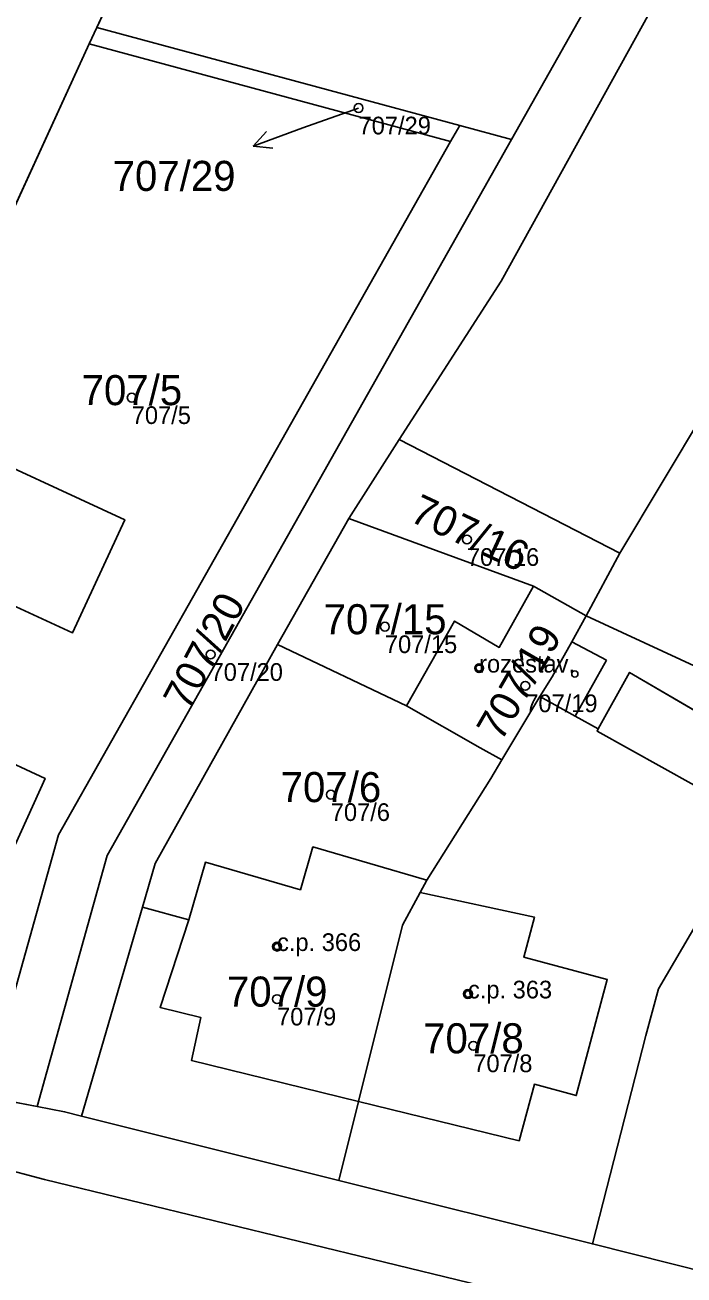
# Model space of a CAD drawing. Extents: x -603967 to -594699, y -1179315 to -1165625.
# Drawn here: x -598433.1 to -598395.8, y -1172192.7 to -1172122 of the extents above; entities that cross this region are included whole.
import ezdxf

# ---------------------------------------------------------------- set-up
doc = ezdxf.new("R2010")
doc.units = 0
for name, color, linetype in [('Definiční body', 7, 'Continuous'), ('Hranice parcel', 7, 'Continuous'), ('Parcelní čísla', 7, 'Continuous'), ('Polygon budovy', 7, 'Continuous'), ('Polygon parcely', 7, 'Continuous'), ('Pop  PČ popisy', 7, 'Continuous'), ('Vnitřní kresba', 7, 'Continuous'), ('Značky budov', 7, 'Continuous')]:
    doc.layers.add(name, color=color, linetype=linetype)

msp = doc.modelspace()

# ---------------------------------------------------------------- linework, layer by layer
at = {"layer": 'Definiční body'}
for centre in [(-598414.22, -1172126.68994), (-598427.05, -1172143.05994), (-598408.09, -1172151.07994), (-598412.73, -1172156.00994), (-598422.59, -1172157.57994), (-598407.4, -1172158.34994), (-598404.79, -1172159.34994), (-598415.79, -1172165.49994), (-598418.83, -1172174.08994), (-598418.83, -1172177.05994), (-598408.03, -1172176.76994), (-598407.73, -1172179.69994)]:
    msp.add_circle(centre, 0.25, dxfattribs=at)
at = {"layer": 'Hranice parcel'}
for p, q in [((-598427.41, -1172118.62), (-598429.02, -1172122.13)), ((-598429.45, -1172123.06), (-598429.02, -1172122.13)), ((-598429.02, -1172122.13), (-598408.49, -1172127.67)), ((-598429.45, -1172123.06), (-598454.41, -1172177.46)), ((-598409.01, -1172128.58), (-598429.45, -1172123.06)), ((-598408.49, -1172127.67), (-598409.01, -1172128.58)), ((-598408.49, -1172127.67), (-598405.56, -1172128.46)), ((-598405.56, -1172128.46), (-598428.45, -1172168.95)), ((-598411.92, -1172145.43), (-598414.77, -1172149.9)), ((-598411.92, -1172145.43), (-598399.44, -1172151.86)), ((-598414.77, -1172149.9), (-598418.8, -1172157.01)), ((-598404.32, -1172153.72), (-598414.77, -1172149.9)), ((-598399.44, -1172151.86), (-598401.34, -1172155.39)), ((-598404.32, -1172153.72), (-598401.34, -1172155.39)), ((-598411.51, -1172160.49), (-598418.8, -1172157.01)), ((-598403.96, -1172159.95), (-598406.11, -1172163.53)), ((-598401.96, -1172161.06), (-598403.96, -1172159.95)), ((-598428.45, -1172168.95), (-598432.4, -1172183.13)), ((-598426.45, -1172171.87), (-598429.9, -1172183.67)), ((-598435.36, -1172182.56), (-598432.4, -1172183.13)), ((-598429.9, -1172183.67), (-598415.34, -1172187.31)), ((-598415.34, -1172187.31), (-598400.99, -1172190.9)), ((-598400.99, -1172190.9), (-598394.33, -1172192.57))]:
    msp.add_line(p, q, dxfattribs=at)
for points in [[(-598343.23, -1172054.29), (-598392.25, -1172139.87), (-598399.44, -1172151.86)], [(-598366.76, -1172065.25), (-598406.16, -1172136.47), (-598411.92, -1172145.43)], [(-598405.56, -1172128.46), (-598370.96, -1172067.25), (-598366.76, -1172065.25)], [(-598434.82, -1172180.65), (-598431.19, -1172167.78), (-598409.01, -1172128.58)], [(-598437.97, -1172161.8), (-598431.95, -1172164.58), (-598434.74, -1172170.72), (-598443.6, -1172166.69), (-598442.75, -1172164.8), (-598445.63, -1172163.48), (-598437.33, -1172145.4), (-598427.45, -1172149.96), (-598430.41, -1172156.36), (-598434.59, -1172154.44), (-598437.97, -1172161.8)], [(-598411.51, -1172160.49), (-598408.79, -1172155.69), (-598406.26, -1172157.18), (-598404.32, -1172153.72)], [(-598401.34, -1172155.39), (-598402.16, -1172156.87), (-598403.26, -1172158.84), (-598403.96, -1172159.95)], [(-598401.34, -1172155.39), (-598391.69, -1172159.86), (-598388.43, -1172161.42)], [(-598418.8, -1172157.01), (-598425.72, -1172169.39), (-598426.45, -1172171.87)], [(-598406.11, -1172163.53), (-598407.35, -1172162.86), (-598411.51, -1172160.49)], [(-598395.24, -1172164.96), (-598400.73, -1172161.91), (-598400.66, -1172161.78), (-598401.96, -1172161.06)], [(-598410.35, -1172170.34), (-598406.74, -1172164.59), (-598406.11, -1172163.53)], [(-598391.7, -1172166.99), (-598397.26, -1172176.48), (-598397.97, -1172179.11), (-598400.99, -1172190.9)], [(-598426.45, -1172171.87), (-598423.83, -1172172.58), (-598422.88, -1172169.32), (-598417.51, -1172170.88), (-598416.8, -1172168.46), (-598410.35, -1172170.34)], [(-598410.35, -1172170.34), (-598410.73, -1172171.04), (-598411.73, -1172172.88), (-598414.22, -1172182.85), (-598415.34, -1172187.31)], [(-598432.4, -1172183.13), (-598430.85, -1172183.43), (-598429.9, -1172183.67)]]:
    msp.add_lwpolyline(points, dxfattribs=at)
at = {"layer": 'Polygon budovy'}
for points in [[(-598437.97, -1172161.8), (-598434.59, -1172154.44), (-598430.41, -1172156.36), (-598427.45, -1172149.96), (-598437.33, -1172145.4), (-598445.63, -1172163.48), (-598442.75, -1172164.8), (-598443.6, -1172166.69), (-598434.74, -1172170.72), (-598431.95, -1172164.58)], [(-598411.51, -1172160.49), (-598407.35, -1172162.86), (-598406.11, -1172163.53), (-598403.96, -1172159.95), (-598403.26, -1172158.84), (-598402.16, -1172156.87), (-598401.34, -1172155.39), (-598404.32, -1172153.72), (-598406.26, -1172157.18), (-598408.79, -1172155.69)], [(-598400.66, -1172161.78), (-598400.73, -1172161.91), (-598395.24, -1172164.96), (-598394.91, -1172165.17), (-598391.7, -1172166.99), (-598388.43, -1172161.42), (-598391.69, -1172159.86), (-598392.9, -1172162.1), (-598398.89, -1172158.59)], [(-598423.83, -1172172.58), (-598425.45, -1172177.53), (-598423.14, -1172178.1), (-598423.67, -1172180.53), (-598414.22, -1172182.85), (-598411.73, -1172172.88), (-598410.73, -1172171.04), (-598410.35, -1172170.34), (-598416.8, -1172168.46), (-598417.51, -1172170.88), (-598422.88, -1172169.32)], [(-598411.73, -1172172.88), (-598414.22, -1172182.85), (-598405.14, -1172185.07), (-598404.27, -1172181.87), (-598401.91, -1172182.51), (-598400.79, -1172178.35), (-598400.15, -1172175.96), (-598404.88, -1172174.69), (-598404.27, -1172172.42), (-598410.73, -1172171.04)]]:
    msp.add_lwpolyline(points, close=True, dxfattribs=at)
at = {"layer": 'Polygon parcely'}
for points in [[(-598346, -1172088.22), (-598308.31, -1172023.09), (-598317.51, -1172020.84), (-598343.23, -1172054.29), (-598392.25, -1172139.87), (-598399.44, -1172151.86), (-598401.34, -1172155.39), (-598391.69, -1172159.86), (-598388.43, -1172161.42), (-598385.73, -1172156.81), (-598378.06, -1172143.31)], [(-598399.44, -1172151.86), (-598392.25, -1172139.87), (-598343.23, -1172054.29), (-598366.76, -1172065.25), (-598406.16, -1172136.47), (-598411.92, -1172145.43)], [(-598427.41, -1172118.62), (-598429.02, -1172122.13), (-598408.49, -1172127.67), (-598405.56, -1172128.46), (-598370.96, -1172067.25), (-598366.76, -1172065.25), (-598364.01, -1172060.34), (-598367.75, -1172062.11), (-598403.85, -1172079.17), (-598410.83, -1172082.12), (-598411.43, -1172082.37), (-598412.86, -1172087)], [(-598428.45, -1172168.95), (-598432.4, -1172183.13), (-598430.85, -1172183.43), (-598429.9, -1172183.67), (-598426.45, -1172171.87), (-598425.72, -1172169.39), (-598418.8, -1172157.01), (-598414.77, -1172149.9), (-598411.92, -1172145.43), (-598406.16, -1172136.47), (-598366.76, -1172065.25), (-598370.96, -1172067.25), (-598405.56, -1172128.46)], [(-598460.01, -1172174.07), (-598460.86, -1172175.93), (-598454.41, -1172177.46), (-598429.45, -1172123.06), (-598429.02, -1172122.13), (-598427.41, -1172118.62), (-598433.32, -1172115.91), (-598434.26, -1172117.63), (-598435.72, -1172120.79), (-598437.07, -1172124.09), (-598441.66, -1172133.89), (-598444.29, -1172139.66), (-598450, -1172152.26)], [(-598429.45, -1172123.06), (-598409.01, -1172128.58), (-598408.49, -1172127.67), (-598429.02, -1172122.13)], [(-598429.45, -1172123.06), (-598454.41, -1172177.46), (-598444.32, -1172180.02), (-598441.78, -1172180.84), (-598441.27, -1172178.91), (-598434.82, -1172180.65), (-598431.19, -1172167.78), (-598409.01, -1172128.58)], [(-598435.36, -1172182.56), (-598432.4, -1172183.13), (-598428.45, -1172168.95), (-598405.56, -1172128.46), (-598408.49, -1172127.67), (-598409.01, -1172128.58), (-598431.19, -1172167.78), (-598434.82, -1172180.65)], [(-598437.97, -1172161.8), (-598431.95, -1172164.58), (-598434.74, -1172170.72), (-598443.6, -1172166.69), (-598442.75, -1172164.8), (-598445.63, -1172163.48), (-598437.33, -1172145.4), (-598427.45, -1172149.96), (-598430.41, -1172156.36), (-598434.59, -1172154.44)], [(-598437.97, -1172161.8), (-598434.59, -1172154.44), (-598430.41, -1172156.36), (-598427.45, -1172149.96), (-598437.33, -1172145.4), (-598445.63, -1172163.48), (-598442.75, -1172164.8), (-598443.6, -1172166.69), (-598434.74, -1172170.72), (-598431.95, -1172164.58)], [(-598404.32, -1172153.72), (-598401.34, -1172155.39), (-598399.44, -1172151.86), (-598411.92, -1172145.43), (-598414.77, -1172149.9)], [(-598414.77, -1172149.9), (-598418.8, -1172157.01), (-598411.51, -1172160.49), (-598408.79, -1172155.69), (-598406.26, -1172157.18), (-598404.32, -1172153.72)], [(-598411.51, -1172160.49), (-598407.35, -1172162.86), (-598406.11, -1172163.53), (-598403.96, -1172159.95), (-598403.26, -1172158.84), (-598402.16, -1172156.87), (-598401.34, -1172155.39), (-598404.32, -1172153.72), (-598406.26, -1172157.18), (-598408.79, -1172155.69)], [(-598403.96, -1172159.95), (-598401.96, -1172161.06), (-598400.66, -1172161.78), (-598400.73, -1172161.91), (-598395.24, -1172164.96), (-598394.91, -1172165.17), (-598391.7, -1172166.99), (-598388.43, -1172161.42), (-598391.69, -1172159.86), (-598401.34, -1172155.39), (-598402.16, -1172156.87), (-598403.26, -1172158.84)], [(-598426.45, -1172171.87), (-598423.83, -1172172.58), (-598422.88, -1172169.32), (-598417.51, -1172170.88), (-598416.8, -1172168.46), (-598410.35, -1172170.34), (-598406.74, -1172164.59), (-598406.11, -1172163.53), (-598407.35, -1172162.86), (-598411.51, -1172160.49), (-598418.8, -1172157.01), (-598425.72, -1172169.39)], [(-598391.7, -1172166.99), (-598397.26, -1172176.48), (-598397.97, -1172179.11), (-598400.99, -1172190.9), (-598394.33, -1172192.57), (-598386.4, -1172194.56), (-598386.11, -1172193.41), (-598385.26, -1172189.95), (-598384.3, -1172186.01), (-598383.07, -1172181.2), (-598382.7, -1172180.09), (-598373.36, -1172163.76), (-598376.38, -1172162.04), (-598382.7, -1172158.44), (-598385.73, -1172156.81), (-598388.43, -1172161.42)], [(-598415.34, -1172187.31), (-598400.99, -1172190.9), (-598397.97, -1172179.11), (-598397.26, -1172176.48), (-598391.7, -1172166.99), (-598394.91, -1172165.17), (-598395.24, -1172164.96), (-598400.73, -1172161.91), (-598400.66, -1172161.78), (-598401.96, -1172161.06), (-598403.96, -1172159.95), (-598406.11, -1172163.53), (-598406.74, -1172164.59), (-598410.35, -1172170.34), (-598410.73, -1172171.04), (-598411.73, -1172172.88), (-598414.22, -1172182.85)], [(-598429.9, -1172183.67), (-598415.34, -1172187.31), (-598414.22, -1172182.85), (-598411.73, -1172172.88), (-598410.73, -1172171.04), (-598410.35, -1172170.34), (-598416.8, -1172168.46), (-598417.51, -1172170.88), (-598422.88, -1172169.32), (-598423.83, -1172172.58), (-598426.45, -1172171.87)]]:
    msp.add_lwpolyline(points, close=True, dxfattribs=at)
msp.add_lwpolyline([(-598394.33, -1172192.57), (-598400.99, -1172190.9), (-598415.34, -1172187.31), (-598429.9, -1172183.67), (-598430.85, -1172183.43), (-598432.4, -1172183.13), (-598435.36, -1172182.56), (-598441.78, -1172180.84), (-598444.32, -1172180.02), (-598454.41, -1172177.46), (-598460.86, -1172175.93), (-598479.25, -1172171.56), (-598499.17, -1172166.38), (-598502.57, -1172165.76), (-598506.46, -1172165.08), (-598504.99, -1172168.27), (-598501.82, -1172175.18), (-598501.14, -1172176.66), (-598500.47, -1172178.12), (-598499.17, -1172178.46), (-598442.4, -1172193.44), (-598434.3, -1172195.58), (-598398.67, -1172204.06), (-598380.14, -1172209.25)], dxfattribs=at)
at = {"layer": 'Pop  PČ popisy'}
for p, q in [((-598414.22, -1172126.69), (-598417.37, -1172127.81)), ((-598417.37, -1172127.81), (-598420.19, -1172128.836)), ((-598420.19, -1172128.836), (-598419.42, -1172128.023)), ((-598420.19, -1172128.836), (-598419.078, -1172128.964))]:
    msp.add_line(p, q, dxfattribs=at)
at = {"layer": 'Vnitřní kresba'}
for p, q in [((-598402.16, -1172156.87), (-598400.19, -1172157.9)), ((-598400.19, -1172157.9), (-598401.96, -1172161.06)), ((-598400.66, -1172161.78), (-598398.89, -1172158.59)), ((-598398.89, -1172158.59), (-598392.9, -1172162.1)), ((-598431.98, -1172187.25), (-598497.9, -1172169.95)), ((-598404.27, -1172172.42), (-598410.73, -1172171.04)), ((-598425.45, -1172177.53), (-598423.83, -1172172.58)), ((-598404.88, -1172174.69), (-598404.27, -1172172.42)), ((-598400.15, -1172175.96), (-598404.88, -1172174.69)), ((-598400.79, -1172178.35), (-598400.15, -1172175.96)), ((-598423.14, -1172178.1), (-598425.45, -1172177.53)), ((-598423.67, -1172180.53), (-598423.14, -1172178.1)), ((-598401.91, -1172182.51), (-598400.79, -1172178.35)), ((-598414.22, -1172182.85), (-598423.67, -1172180.53)), ((-598405.14, -1172185.07), (-598404.27, -1172181.87)), ((-598404.27, -1172181.87), (-598401.91, -1172182.51)), ((-598405.14, -1172185.07), (-598414.22, -1172182.85)), ((-598395.71, -1172196.06), (-598431.98, -1172187.25))]:
    msp.add_line(p, q, dxfattribs=at)
at = {"layer": 'Značky budov'}
for centre in [(-598407.4068, -1172158.34916), (-598401.9868, -1172158.67916), (-598418.8368, -1172174.08916), (-598408.0368, -1172176.76916)]:
    msp.add_circle(centre, 0.175, dxfattribs=at)

# ---------------------------------------------------------------- texts
at = {"layer": 'Definiční body'}
for s, p in [('707/29', (-598414.22, -1172128.179)), ('707/5', (-598427.05, -1172144.549)), ('707/16', (-598408.09, -1172152.569)), ('707/15', (-598412.73, -1172157.499)), ('707/20', (-598422.59, -1172159.069)), ('rozestav.', (-598407.4, -1172158.6)), ('707/19', (-598404.79, -1172160.839)), ('707/6', (-598415.79, -1172166.989)), ('c.p. 366', (-598418.83, -1172174.34)), ('c.p. 363', (-598408.03, -1172177.02)), ('707/9', (-598418.83, -1172178.549)), ('707/8', (-598407.73, -1172181.189))]:
    msp.add_text(s, height=0.999996, dxfattribs=at).set_placement(p)
at = {"layer": 'Parcelní čísla'}
for s, p in [('707/29', (-598428.132, -1172131.375)), ('707/5', (-598429.886, -1172143.485)), ('707/15', (-598416.196, -1172156.435)), ('707/6', (-598418.626, -1172165.925)), ('707/9', (-598421.666, -1172177.485)), ('707/8', (-598410.566, -1172180.125))]:
    msp.add_text(s, height=1.699998, dxfattribs=at).set_placement(p)
for s, rotation, p in [('707/16', 335, (-598411.411, -1172150)), ('707/20', 62, (-598423.842, -1172160.84)), ('707/19', 59.9999972, (-598406.155, -1172162.564))]:
    msp.add_text(s, height=1.699998, rotation=rotation, dxfattribs=at).set_placement(p)

doc.saveas('drawing.dxf')
